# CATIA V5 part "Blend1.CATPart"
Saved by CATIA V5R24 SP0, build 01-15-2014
Part number: Part1
Bounding box of the stored display mesh (mm): x -120 to 0, y -147 to 60, z -61 to 0
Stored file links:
  E:\Desktop_RNH\학부 CAD 수업 자료\[CAD_V2]강의자료(CAD)_2017년 이후\툴바예제\4 GSD\Surfaces\Upload2\Blend1.CATPart

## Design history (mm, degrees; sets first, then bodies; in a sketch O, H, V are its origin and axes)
Set1 "Geometrical_Set.1"
  Point1: type OnPlane, Support xy-plane, H -100, V -100, Direction (1, 0, 0)
  Point2: type OnPlane, Support xy-plane, H -40, V -100, Direction (1, 0, 0)
  Line1: type PtPt, FirstPoint Point1, SecondPoint Point2, Support xy-plane
  Extrude1: Element1 Line1, Lim1 25, Lim2 47, Direction zx-plane
  Plane1: type Offset, RefPlane xy-plane, Offset -61
  Point3: type OnPlane, Support Plane1, H 0, V -20, Direction (1, 0, 0)
  Point4: type OnPlane, Support Plane1, H -120, V -20, Direction (1, 0, 0)
  Line2: type PtPt, FirstPoint Point3, SecondPoint Point4, Support Plane1
  Extrude2: Element1 Line2, Lim1 0, Lim2 -80, Direction zx-plane
Body1 (main body)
